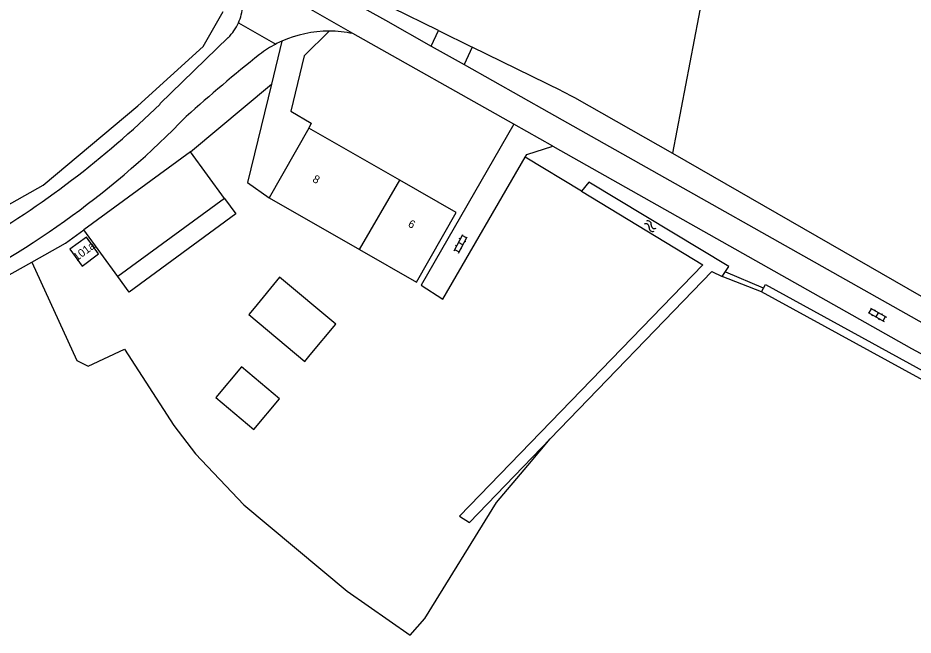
# Model space of a CAD drawing. Extents: x 132994 to 136000, y 393499 to 395512.
# Drawn here: x 133449.1 to 133560.9, y 393861.4 to 393938.5 of the extents above; entities that cross this region are included whole.
import ezdxf

# ---------------------------------------------------------------- set-up
doc = ezdxf.new("R2010")
doc.units = 0
for name, color, linetype in [('gg-anno-huisnummerreeks BGT', 7, 'Continuous'), ('gg-bbg-bijgebouw', 7, 'Continuous'), ('gg-bbg-gedigitaliseerde bijgebouw', 7, 'Continuous'), ('gg-bbg-hoofdgebouw', 7, 'Continuous'), ('gg-bbg-luifel en loopbrug', 7, 'Continuous'), ('gg-bbg-tussenscheiding', 7, 'Continuous'), ('gg-knt-bronhoudergrens', 7, 'Continuous'), ('gg-knt-verharding', 7, 'Continuous'), ('gg-kntw-bovenkant insteek waterloop', 7, 'Continuous'), ('gg-kwrk-duiker nz buis', 7, 'Continuous'), ('gt-grn-groengrens', 7, 'Continuous'), ('gt-grn-weggrens', 7, 'Continuous'), ('gt-symb-klinker verharding', 7, 'Continuous'), ('gt-symb-watersymbool', 7, 'Continuous'), ('gx-grn-maaiveld', 7, 'Continuous')]:
    doc.layers.add(name, color=color, linetype=linetype)

# ---------------------------------------------------------------- blocks, each defined once
blk = doc.blocks.new('gt0-WA')
at = {"layer": 'gt-symb-watersymbool'}
for centre, start, end in [((-0.32, 0.02), 28.0725, 151.9275), ((0.43, 0.42), 208.0725, 331.9275), ((-0.32, -0.43), 28.0725, 151.9275), ((0.43, -0.03), 208.0725, 331.9275)]:
    blk.add_arc(centre, 0.425, start, end, dxfattribs=at)
blk = doc.blocks.new('gt0-KL1')
at = {"layer": 'gt-symb-klinker verharding'}
for p, q in [((-1.15, 0.3), (1.15, 0.3)), ((-1, -0.3), (-1, 0.3)), ((-0.5, 0.3), (-0.5, 0.45)), ((0, -0.3), (0, 0.3)), ((0.5, 0.3), (0.5, 0.45)), ((1, -0.3), (1, 0.3)), ((-1.15, -0.3), (1.15, -0.3)), ((-0.5, -0.45), (-0.5, -0.3)), ((0.5, -0.45), (0.5, -0.3))]:
    blk.add_line(p, q, dxfattribs=at)

msp = doc.modelspace()

# ---------------------------------------------------------------- linework, layer by layer
at = {"layer": 'gg-bbg-bijgebouw'}
msp.add_line((133470.69, 393921.77), (133457.36, 393912.01), dxfattribs=at)
msp.add_lwpolyline([(133484.98, 393895.6), (133485.65, 393896.4), (133488.85, 393900.24), (133481.83, 393906.09), (133478.63, 393902.25), (133477.97, 393901.46), (133484.98, 393895.6)], dxfattribs=at)
at = {"layer": 'gg-bbg-gedigitaliseerde bijgebouw'}
msp.add_lwpolyline([(133481.8, 393890.94), (133477.05, 393894.91), (133473.84, 393891.08), (133478.59, 393887.11), (133481.8, 393890.94)], dxfattribs=at)
at = {"layer": 'gg-bbg-hoofdgebouw'}
for p, q in [((133485.47, 393924.7), (133480.5, 393916.02)), ((133496.83, 393918.21), (133485.47, 393924.7)), ((133480.5, 393916.02), (133491.79, 393909.57))]:
    msp.add_line(p, q, dxfattribs=at)
for points in [[(133491.79, 393909.57), (133498.92, 393905.49), (133503.88, 393914.18), (133496.83, 393918.21)], [(133457.15, 393907.49), (133459.22, 393909.01), (133457.69, 393911.11), (133455.62, 393909.6), (133457.15, 393907.49)]]:
    msp.add_lwpolyline(points, dxfattribs=at)
at = {"layer": 'gg-bbg-luifel en loopbrug'}
msp.add_line((133474.93, 393915.95), (133461.62, 393906.2), dxfattribs=at)
msp.add_lwpolyline([(133474.93, 393915.95), (133476.36, 393914), (133463.05, 393904.25), (133461.62, 393906.2)], dxfattribs=at)
at = {"layer": 'gg-bbg-tussenscheiding'}
msp.add_line((133491.79, 393909.57), (133496.83, 393918.21), dxfattribs=at)
at = {"layer": 'gg-knt-bronhoudergrens'}
msp.add_line((133542, 393904.29), (133537.1, 393906.2), dxfattribs=at)
msp.add_lwpolyline([(133530.89, 393921.57), (133565.29, 393901.81), (133576.27, 393896.51), (133586.45, 393893.34), (133590.6, 393892.4)], dxfattribs=at)
at = {"layer": 'gg-knt-verharding'}
for p, q in [((133511.09, 393925.19), (133490.97, 393936.52)), ((133515.95, 393922.45), (133511.09, 393925.19)), ((133515.95, 393922.45), (133560.74, 393897.22))]:
    msp.add_line(p, q, dxfattribs=at)
for points in [[(133480.79, 393930.19), (133477.82, 393917.93), (133480.5, 393916.02)], [(133511.09, 393925.19), (133499.49, 393905.13), (133502.22, 393903.37), (133512.48, 393921.1)], [(133512.48, 393921.1), (133512.68, 393921.44), (133515.95, 393922.45)]]:
    msp.add_lwpolyline(points, dxfattribs=at)
msp.add_arc((133616.07, 393993.59), 111.13, 240.1362, 250.394, dxfattribs=at)
at = {"layer": 'gg-kntw-bovenkant insteek waterloop'}
for p, q in [((133519.52, 393916.84), (133534.69, 393907.66)), ((133515.61, 393885.92), (133535.8, 393906.8)), ((133535.8, 393906.8), (133537.1, 393906.2)), ((133578.81, 393884.11), (133542, 393904.29))]:
    msp.add_line(p, q, dxfattribs=at)
for points in [[(133537.1, 393906.2), (133537.92, 393907.46), (133520.46, 393917.95), (133519.52, 393916.84)], [(133534.69, 393907.66), (133504.31, 393876.29), (133505.52, 393875.49), (133515.61, 393885.92)], [(133542, 393904.29), (133542.5, 393905.19), (133579.31, 393885.01), (133578.81, 393884.11)]]:
    msp.add_lwpolyline(points, dxfattribs=at)
at = {"layer": 'gg-kwrk-duiker nz buis'}
msp.add_line((133537.53, 393906.77), (133542.21, 393904.77), dxfattribs=at)
at = {"layer": 'gt-grn-groengrens'}
for p, q in [((133470.69, 393921.77), (133480.79, 393930.19)), ((133519.52, 393916.84), (133512.48, 393921.1))]:
    msp.add_line(p, q, dxfattribs=at)
at = {"layer": 'gt-grn-weggrens'}
msp.add_line((133490.97, 393936.52), (133474.01, 393946.26), dxfattribs=at)
at = {"layer": 'gx-grn-maaiveld'}
for p, q in [((133476.67, 393937.86), (133481.36, 393935.2)), ((133495.03, 393938.19), (133500.77, 393934.95)), ((133500.77, 393934.95), (133501.66, 393936.9)), ((133501.66, 393936.9), (133505.88, 393934.83)), ((133466.88, 393927.73), (133475.41, 393936.01)), ((133482.1, 393935.56), (133480.79, 393930.19)), ((133500.77, 393934.95), (133504.88, 393932.64)), ((133505.88, 393934.83), (133504.88, 393932.64)), ((133517.01, 393929.37), (133505.88, 393934.83)), ((133504.88, 393932.64), (133515.48, 393926.67)), ((133515.48, 393926.67), (133562.34, 393900.29)), ((133474.93, 393915.95), (133470.69, 393921.77)), ((133461.62, 393906.2), (133457.36, 393912.01))]:
    msp.add_line(p, q, dxfattribs=at)
for points in [[(133431.86, 394118.01), (133430.95, 394118.33), (133428.63, 394118.73), (133427.18, 394121.35), (133432.09, 394124.53), (133447.16, 394082.63), (133454.47, 394061.12), (133457.27, 394047.74), (133461.58, 394022.03), (133464.76, 394003.61), (133467.13, 394001.82), (133483.93, 393993.48), (133489.48, 393991.63), (133494.24, 393990.59), (133500.7, 393990.2), (133507.89, 393990.52), (133541.21, 393993.62), (133537.4, 393955.59), (133530.89, 393921.57)], [(133501.66, 393936.9), (133495.9, 393939.72), (133491.45, 393942.24)], [(133490.58, 393940.7), (133492.71, 393939.49), (133495.03, 393938.19)], [(133408.22, 393895.16), (133433.05, 393906.79), (133452.28, 393917.59), (133464.11, 393927.5), (133472.26, 393934.92), (133474.77, 393939.29)], [(133488.01, 393936.82), (133484.9, 393933.74), (133483.21, 393926.85), (133485.78, 393925.35), (133485.47, 393924.7)], [(133517.01, 393929.37), (133518.66, 393928.54), (133530.89, 393921.57)], [(133450.89, 393908), (133455.08, 393910.34), (133457.36, 393912.01)], [(133416.67, 393890.65), (133439.96, 393901.9), (133450.89, 393908)], [(133450.89, 393908), (133456.48, 393895.72), (133457.93, 393895), (133462.46, 393897.11), (133468.62, 393887.59), (133471.3, 393884.05), (133477.37, 393877.67), (133490.26, 393866.9), (133498.11, 393861.43), (133499.97, 393863.51), (133508.92, 393877.98), (133512.82, 393882.61), (133515.61, 393885.92)]]:
    msp.add_lwpolyline(points, dxfattribs=at)
for centre, radius, start, end in [((133470.68, 393940.58), 6.58, 335.6544, 354.3619), ((133470.66, 393940.58), 6.6, 316.1003, 335.6544), ((133488.02, 393922.32), 14.5, 90.0194, 114.0974), ((133488.02, 393922.3), 14.52, 78.2553, 90.013), ((133488, 393922.37), 14.46, 114.1279, 117.376), ((133488.05, 393922.29), 14.55, 117.3762, 126.9932), ((133625.21, 393752.55), 232.77, 128.8201, 131.7668), ((133384.65, 394011.96), 117.72, 300.1104, 314.3114), ((133390.59, 394003.46), 110.94, 296.3201, 315.8304)]:
    msp.add_arc(centre, radius, start, end, dxfattribs=at)

# ---------------------------------------------------------------- block references
at = {"layer": 'gt-symb-klinker verharding'}
for p, rotation in [((133504.43, 393910.28), 61.97468393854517), ((133556.47, 393901.41), -29.410819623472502)]:
    msp.add_blockref('gt0-KL1', p, dxfattribs=dict(at, rotation=rotation))
at = {"layer": 'gt-symb-watersymbool', "rotation": 144.1958940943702}
msp.add_blockref('gt0-WA', (133528.15, 393912.44), dxfattribs=at)

# ---------------------------------------------------------------- texts
at = {"layer": 'gg-anno-huisnummerreeks BGT'}
for s, rotation, p in [('8', 330.2, (133485.84, 393918.08)), ('6', 330.3, (133497.77, 393912.49)), ('101a', 36.3, (133456.49, 393908.08))]:
    msp.add_text(s, height=1, rotation=rotation, dxfattribs=at).set_placement(p)

doc.saveas('drawing.dxf')
